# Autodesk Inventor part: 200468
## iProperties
Created: 2007-10
Part Number: 200468
Document SubType Name: Modeling
Designer: TH
Density: 7.85 g/cm^3
Mass: 510.334 g
Surface Area: 671.811 cm^2
Volume: 65.0106 cm^3
Material: Steel
Description: RAIL SIDE - RIGHT OUTER
Component Category: Lower Component
Author: TH
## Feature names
1. Extrusion1
2. Fillet1
3. Extrusion2
4. Extrusion3
5. Fillet2
6. Fillet3
7. Extrusion4
8. Fillet4
9. Fillet5
10. Hole1
11. Hole2
